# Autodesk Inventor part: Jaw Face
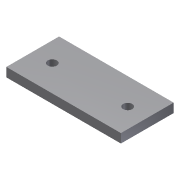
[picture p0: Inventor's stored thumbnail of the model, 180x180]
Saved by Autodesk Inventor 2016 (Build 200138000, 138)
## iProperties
Shininess: 77.0
Length Units: 11269
Angle Units: 11279
Time Units: 11290
Mass Units: 11283
Length Display Precision: 3
Angle Display Precision: 2
Compacted: True
Created: 2002-02
Part Number: Jaw Face
Document SubType Name: Modeling
Designer: ***
Density: 1 g/cm^3
Material: Generic
Appearance: Default
Density: 0.0
Volumn: 0.0
Area: 0.0
PropertySet Name: Model Information
Control State: 0
Master: False
Checked Out: False
Author: ***
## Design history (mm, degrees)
sketch "Sketch1"
  geometry: L1 (-79.661, -8.43)-(-3.661, -8.43); L2 (-3.661, -8.43)-(-3.661, -43.43); L3 (-3.661, -43.43)-(-79.661, -43.43); L4 (-79.661, -43.43)-(-79.661, -8.43); C1 r 3 at (-66.661, -25.93); C2 r 3 at (-16.661, -25.93)
  constraints: 8 end point, 2 centre point, 2 parallel, 1 equal radius, 1 horizontal, 1 perpendicular
  dimensions: "d0" = 76 distance of L2.end L3.end; "d1" = 6 diameter of C1; "d2" = 50 distance of C2.centre C1.centre; "d3" = 35 distance of L1.end L2.end; "d4" = 17.5 distance from line of L3 C2.centre; "d5" = 13 distance from line of L2 C2.centre; "d6" = 13 distance from line of L4 C1.centre
extrude "Extrusion1" new body sketch "Sketch1" stored distance "d7" = 6; taper "d8" = 0 deg
body "Solid1"
